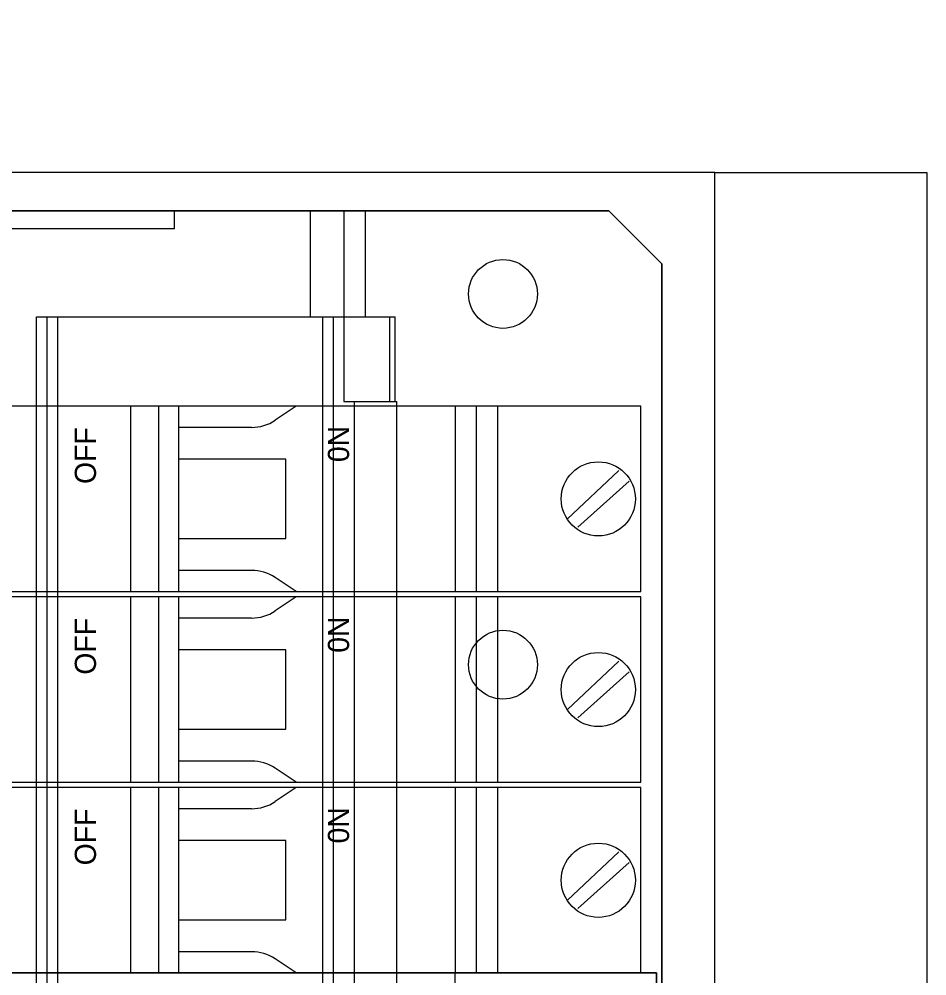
# Model space of a CAD drawing. Extents: x 0 to 4205, y 0 to 2970.
# Drawn here: x 1101.4 to 1187, y 1137.3 to 1227.6 of the extents above; entities that cross this region are included whole.
import ezdxf

# ---------------------------------------------------------------- set-up
doc = ezdxf.new("R2010")
doc.units = 0
doc.layers.add('Level 1', color=7, linetype='Continuous')

# ---------------------------------------------------------------- blocks, each defined once
blk = doc.blocks.new('NCX-2418-3U')
for p, q in [((-57.258, 142.85), (10, 142.85)), ((-31, 141.15), (-31, 142.85)), ((-18.2, 142.85), (-18.2, 132.85)), ((-15, 142.85), (-15, 124.85)), ((-13, 142.85), (-13, 132.85)), ((15, 137.85), (10, 142.85)), ((-31, 141.15), (-57, 141.15)), ((15, 137.85), (15, -94.15)), ((-44, -99.15), (-44, 132.85)), ((-44, 132.85), (-10.17, 132.85)), ((-43, -99.15), (-43, 132.85)), ((-42, -99.15), (-42, 132.85)), ((-17, -99.15), (-17, 132.85)), ((-16, -99.15), (-16, 132.85)), ((-10.67, 124.85), (-10.67, 132.85)), ((-10.17, 124.85), (-10.17, 132.85)), ((-15, 124.85), (-10, 124.85)), ((-14, -91.15), (-14, 124.85)), ((-10, -91.15), (-10, 124.85))]:
    blk.add_line(p, q)
blk.add_lwpolyline([(15, -94.15), (15, 137.85), (10, 142.85), (-57.258, 142.85), (-57.258, 163.65)])
for centre in [(0, 135), (0, 100)]:
    blk.add_circle(centre, 3.25)

msp = doc.modelspace()

# ---------------------------------------------------------------- linework, layer by layer
at = {"layer": 'Level 1'}
for p, q in [((1160.008, 1191.093), (1077.008, 1191.093)), ((1111.855, 1191.093), (1111.855, 1173.593)), ((1114.508, 1191.093), (1114.508, 1173.593)), ((1116.423, 1173.65), (1116.423, 1191.069)), ((1127.508, 1191.093), (1125.515, 1189.765)), ((1142.508, 1191.093), (1142.508, 1173.593)), ((1144.508, 1173.593), (1144.508, 1191.093)), ((1146.508, 1191.093), (1146.508, 1173.593)), ((1160.008, 1173.593), (1160.008, 1191.093)), ((1123.297, 1189.093), (1116.423, 1189.093)), ((1126.508, 1186.093), (1116.423, 1186.093)), ((1126.508, 1178.593), (1126.508, 1186.093)), ((1157.932, 1185.017), (1153.084, 1180.419)), ((1154.084, 1179.669), (1158.932, 1184.017)), ((1116.423, 1178.593), (1126.508, 1178.593)), ((1123.297, 1175.593), (1116.423, 1175.593)), ((1127.508, 1173.593), (1125.515, 1174.921)), ((1077.008, 1173.593), (1160.008, 1173.593)), ((1160.008, 1173.093), (1077.008, 1173.093)), ((1111.855, 1173.093), (1111.855, 1155.593)), ((1114.508, 1173.093), (1114.508, 1155.593)), ((1116.423, 1155.65), (1116.423, 1173.069)), ((1127.508, 1173.093), (1125.515, 1171.765)), ((1142.508, 1173.093), (1142.508, 1155.593)), ((1144.508, 1155.593), (1144.508, 1173.093)), ((1146.508, 1173.093), (1146.508, 1155.593)), ((1160.008, 1155.593), (1160.008, 1173.093)), ((1123.297, 1171.093), (1116.423, 1171.093)), ((1126.508, 1168.093), (1116.423, 1168.093)), ((1126.508, 1160.593), (1126.508, 1168.093)), ((1157.932, 1167.017), (1153.084, 1162.419)), ((1154.084, 1161.669), (1158.932, 1166.017)), ((1116.423, 1160.593), (1126.508, 1160.593)), ((1123.297, 1157.593), (1116.423, 1157.593)), ((1127.508, 1155.593), (1125.515, 1156.921)), ((1077.008, 1155.593), (1160.008, 1155.593)), ((1160.008, 1155.093), (1077.008, 1155.093)), ((1111.855, 1155.093), (1111.855, 1137.593)), ((1114.508, 1155.093), (1114.508, 1137.593)), ((1116.423, 1137.65), (1116.423, 1155.069)), ((1127.508, 1155.093), (1125.515, 1153.765)), ((1142.508, 1155.093), (1142.508, 1137.593)), ((1144.508, 1137.593), (1144.508, 1155.093)), ((1146.508, 1155.093), (1146.508, 1137.593)), ((1160.008, 1137.593), (1160.008, 1155.093)), ((1123.297, 1153.093), (1116.423, 1153.093)), ((1126.508, 1150.093), (1116.423, 1150.093)), ((1126.508, 1142.593), (1126.508, 1150.093)), ((1157.932, 1149.017), (1153.084, 1144.419)), ((1154.084, 1143.669), (1158.932, 1148.017)), ((1116.423, 1142.593), (1126.508, 1142.593)), ((1123.297, 1139.593), (1116.423, 1139.593)), ((1127.508, 1137.593), (1125.515, 1138.921)), ((1077.008, 1137.593), (1160.008, 1137.593)), ((1142.508, 1101.593), (1142.508, 1137.593))]:
    msp.add_line(p, q, dxfattribs=at)
msp.add_lwpolyline([(1089.987, 963.143), (1167.008, 963.143), (1167.008, 1213.143), (1089.749, 1213.143)], dxfattribs=at)
for points in [[(1187.008, 963.143), (1167.008, 963.143), (1167.008, 1213.143), (1187.008, 1213.143)], [(1160.008, 1173.593), (1160.008, 1191.093), (1077.008, 1191.093), (1077.008, 1173.593)], [(1160.008, 1173.593), (1160.008, 1191.093), (1077.008, 1191.093), (1077.008, 1173.593)], [(1160.008, 1155.593), (1160.008, 1173.093), (1077.008, 1173.093), (1077.008, 1155.593)], [(1160.008, 1155.593), (1160.008, 1173.093), (1077.008, 1173.093), (1077.008, 1155.593)], [(1160.008, 1137.593), (1160.008, 1155.093), (1077.008, 1155.093), (1077.008, 1137.593)], [(1160.008, 1137.593), (1160.008, 1155.093), (1077.008, 1155.093), (1077.008, 1137.593)], [(1161.508, 1101.593), (1161.508, 1137.593), (1075.508, 1137.593), (1075.508, 1101.593)], [(1075.508, 1101.593), (1075.508, 1137.593), (1161.508, 1137.593), (1161.508, 1101.593)]]:
    msp.add_lwpolyline(points, close=True, dxfattribs=at)
for centre in [(1156.008, 1182.343), (1156.008, 1164.343), (1156.008, 1146.343)]:
    msp.add_circle(centre, 3.5, dxfattribs=at)
for centre, start, end in [((1123.297, 1193.093), 270, 303.69007), ((1123.297, 1171.593), 56.30993, 90), ((1123.297, 1175.093), 270, 303.69007), ((1123.297, 1153.593), 56.30993, 90), ((1123.297, 1157.093), 270, 303.69007), ((1123.297, 1135.593), 56.30993, 90)]:
    msp.add_arc(centre, 4, start, end, dxfattribs=at)

# ---------------------------------------------------------------- block references
msp.add_blockref('NCX-2418-3U', (1147.008, 1066.693))

# ---------------------------------------------------------------- texts
for s, p in [('OFF', (1108.609, 1183.752)), ('0N', (1132.49, 1185.818)), ('OFF', (1108.609, 1165.752)), ('0N', (1132.49, 1167.818)), ('OFF', (1108.609, 1147.752)), ('0N', (1132.49, 1149.818))]:
    msp.add_text(s, height=2, rotation=90, dxfattribs=at).set_placement(p)

doc.saveas('drawing.dxf')
